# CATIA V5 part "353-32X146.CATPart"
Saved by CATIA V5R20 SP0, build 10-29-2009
Part number: 353-32X146
Definition: NONE
Nomenclature: 353-32X146
Source: Unknown
Description: 353-32X146
Bounding box of the stored display mesh (mm): x -7 to 139, y -22.5 to 22.5, z -22.5 to 22.5
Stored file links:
  C:\Users\Utente\Desktop\IO LAVORO\3D X SITO CF\X SITO\PLASTICA\353\353-32X146.CATPart
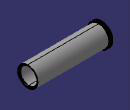
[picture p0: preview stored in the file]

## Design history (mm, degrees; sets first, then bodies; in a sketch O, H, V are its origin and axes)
Body1 "353-32X146" (main body)
  Solid1: solid without history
